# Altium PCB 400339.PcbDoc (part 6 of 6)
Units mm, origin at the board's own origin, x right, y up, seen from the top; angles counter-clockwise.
Board outline 146 x 63.5 mm, 4 copper layers (Top Layer, Mid-Layer 1, Mid-Layer 2, Bottom Layer), stack 1.505 mm thick; 400 components, 261 nets, 1523 pads, 1938 vias.
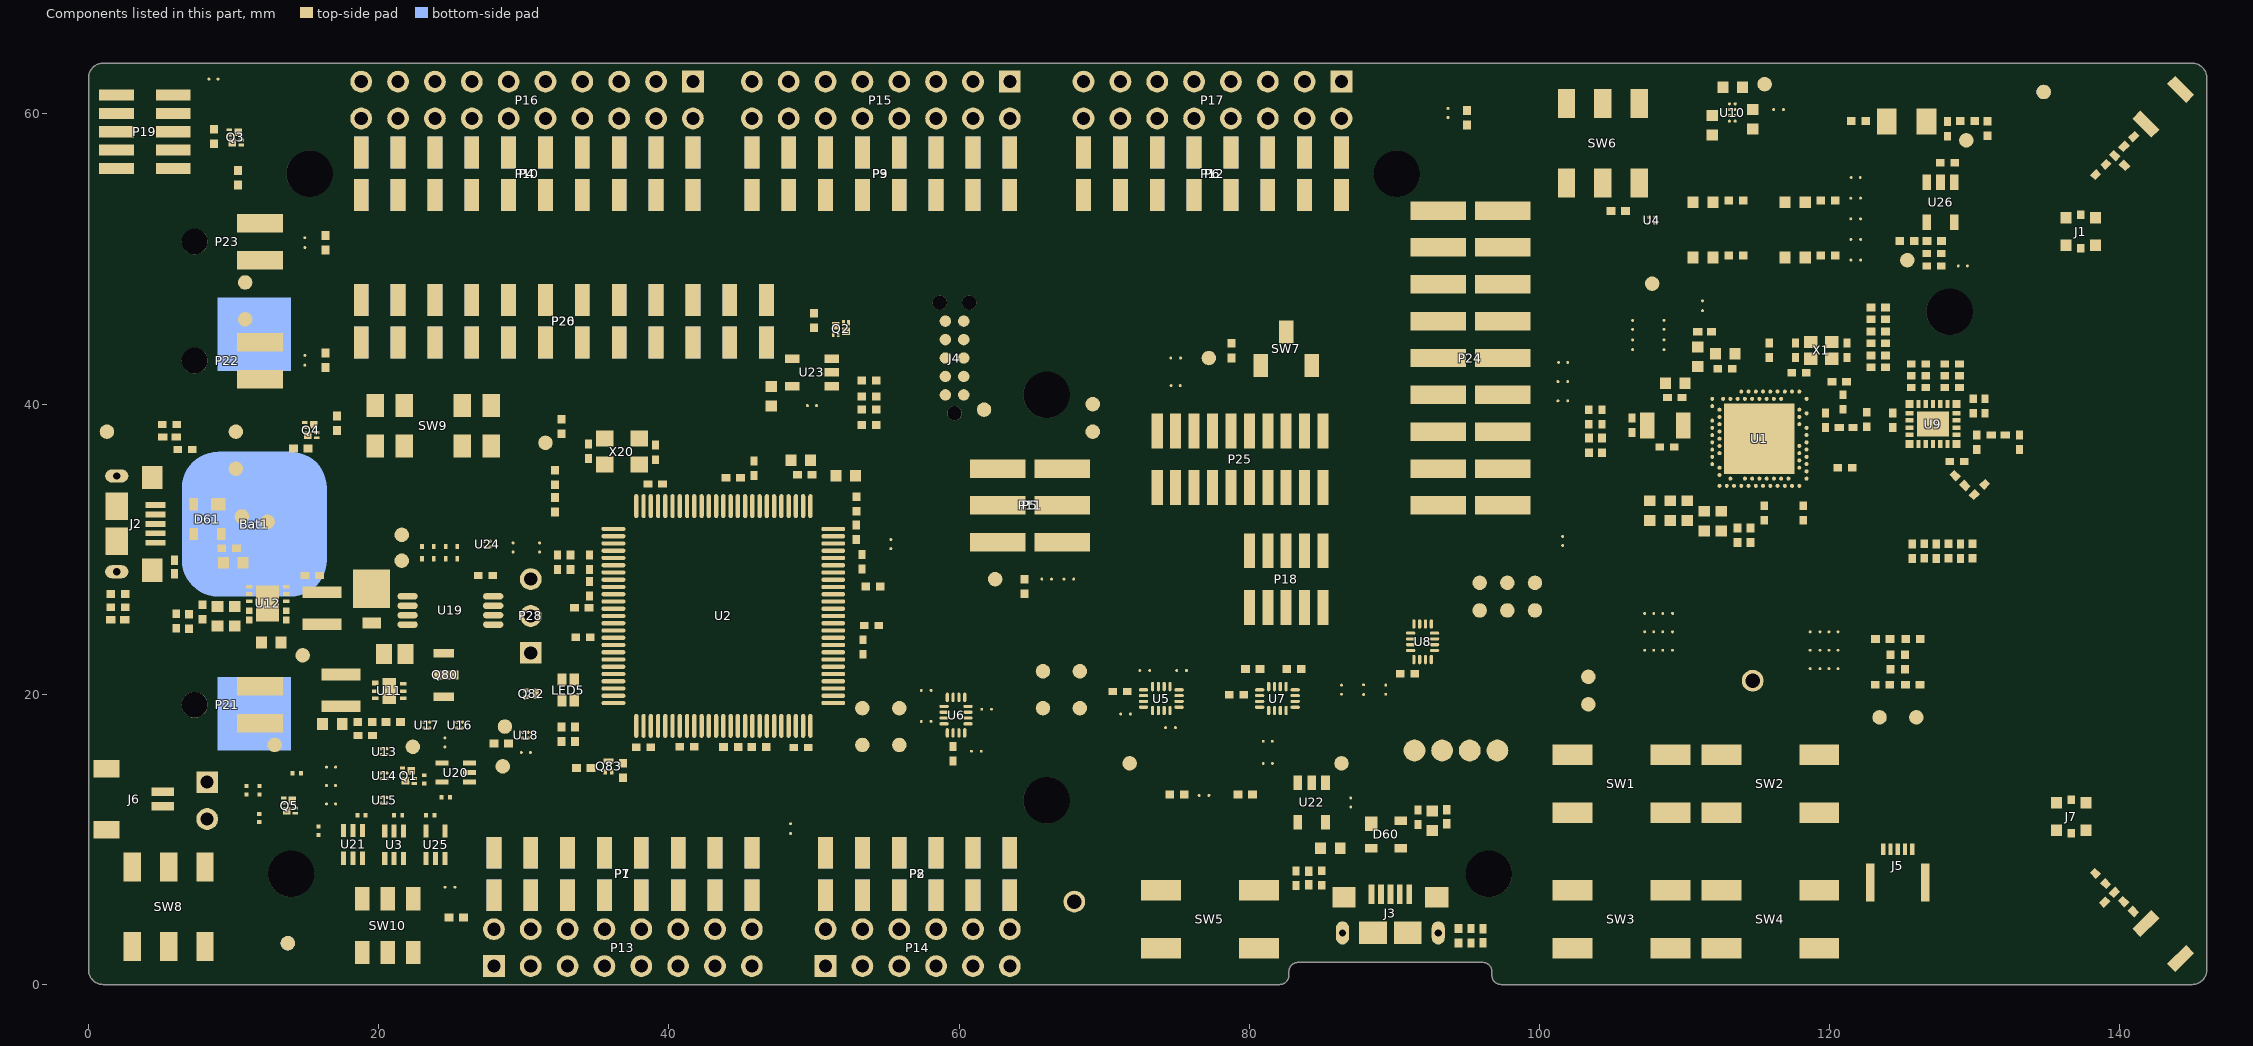
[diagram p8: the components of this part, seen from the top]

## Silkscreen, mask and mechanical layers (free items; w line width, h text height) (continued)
Bottom Overlay:
  drawing of 1284 lines, arcs and shapes, not listed
  text "J-Link" at 117.897,62.424 h1.45 r90
  text "www.segger.com" at 119.047,62.343 h1.68 r90
  text "Pb" at 6.415,60.623 h3.05 r90
  text "TM" at 117.475,58.954 h0.94 r90
  text "S" at 116.037,58.741 h1.35 r90
  text "E" at 116.037,57.851 h1.35 r90
  text "Technology" at 117.897,57.672 h1.45 r90
  text "G" at 116.037,57.067 h1.35 r90
  text "G" at 116.037,56.077 h1.35 r90
  text "E" at 116.037,55.053 h1.35 r90
  text "R" at 116.037,54.217 h1.35 r90
  text "P0.27" at 19.303,53.111 h1.65 r90
  text "P0.26" at 21.843,53.111 h1.65 r90
  text "P0.02" at 24.383,53.111 h1.65 r90
  text "GND" at 26.924,53.111 h1.65 r90
  text "P1.15" at 29.463,53.111 h1.65 r90
  text "P1.14" at 32.003,53.111 h1.65 r90
  text "P1.13" at 34.543,53.111 h1.65 r90
  text "P1.12" at 37.083,53.111 h1.65 r90
  text "P1.11" at 39.623,53.111 h1.65 r90
  text "P1.10" at 42.163,53.111 h1.65 r90
  text "P1.08" at 46.227,53.111 h1.65 r90
  text "P1.07 (D6)" at 48.768,53.111 h1.65 r90
  text "P1.06 (D5)" at 51.308,53.111 h1.65 r90
  text "P1.05 (D4)" at 53.848,53.111 h1.65 r90
  text "P1.04 (D3)" at 56.388,53.111 h1.65 r90
  text "P1.03 (D2)" at 58.928,53.111 h1.65 r90
  text "P1.02 (D1)" at 61.468,53.111 h1.65 r90
  text "P1.01 (ARDUINO D0)" at 64.008,53.111 h1.65 r90
  text "P0.10" at 69.088,53.111 h1.78 r90
  text "P0.09" at 71.628,53.111 h1.78 r90
  text "P0.08" at 74.168,53.111 h1.78 r90
  text "P0.07" at 76.708,53.111 h1.78 r90
  text "P0.06" at 79.248,53.111 h1.78 r90
  text "P0.05" at 81.788,53.111 h1.78 r90
  text "P0.01" at 84.328,53.111 h1.78 r90
  text "P0.00" at 86.843,53.111 h1.78 r90
  text "(SCL)" at 20.421,52.07 h1.65 r90
  text "(SDA)" at 22.961,52.07 h1.65 r90
  text "(AREF)" at 25.501,52.07 h1.65 r90
  text "(D13)" at 30.581,52.07 h1.65 r90
  text "(D12)" at 33.121,52.07 h1.65 r90
  text "(D11)" at 35.661,52.07 h1.65 r90
  text "(D10)" at 38.201,52.07 h1.65 r90
  text "(D9)" at 40.741,52.07 h1.65 r90
  text "(D8)" at 43.281,52.07 h1.65 r90
  text "(D7)" at 47.345,52.07 h1.65 r90
  text "GPIO" at 76.911,48.701 h1.99 r90
  text "P0.00" at 80.747,48.641 h1.91 r90
  text "P0.01" at 86.131,48.641 h1.91 r90
  text "P0.11" at 90.17,48.641 h1.91 r90
  text "P0.12" at 92.862,48.641 h1.91 r90
  text "P0.24" at 95.555,48.641 h1.91 r90
  text "P0.25" at 98.247,48.641 h1.91 r90
  text "P0.13" at 100.94,48.641 h1.91 r90
  text "P0.14" at 103.632,48.641 h1.91 r90
  text "P0.15" at 106.324,48.641 h1.91 r90
  text "P0.16" at 109.017,48.641 h1.91 r90
  text "P0.17" at 111.709,48.641 h1.91 r90
  text "P0.19" at 114.402,48.641 h1.91 r90
  text "P0.20" at 117.094,48.641 h1.91 r90
  text "P0.21" at 119.786,48.641 h1.91 r90
  text "P0.22" at 122.479,48.641 h1.91 r90
  text "P0.23" at 125.171,48.641 h1.91 r90
  text "ANT_SEL" at 125.171,43.514 h1.91 r90
  text "Function" at 76.911,43.231 h1.99 r90
  text "Button 4" at 98.247,42.965 h1.91 r90
  text "Button 2" at 92.862,42.942 h1.91 r90
  text "Button 3" at 95.555,42.949 h1.91 r90
  text "Button 1" at 90.17,42.846 h1.91 r90
  text "LED 4" at 109.017,41.922 h1.91 r90
  text "LED 2" at 103.632,41.899 h1.91 r90
  text "LED 3" at 106.324,41.905 h1.91 r90
  text "GPIO" at 27.33,41.805 h1.99 r90
  text "P0.05" at 29.82,41.783 h1.91 r90
  text "P0.06" at 32.512,41.783 h1.91 r90
  text "P0.07" at 35.204,41.783 h1.91 r90
  text "P0.08" at 37.897,41.783 h1.91 r90
  text "P0.18" at 40.589,41.783 h1.91 r90
  text "P1.00" at 43.282,41.783 h1.91 r90
  text "P0.09" at 52.222,41.783 h1.91 r90
  text "P0.10" at 56.794,41.783 h1.91 r90
  text "LED 1" at 100.94,41.803 h1.91 r90
  text "CTX" at 111.709,41.476 h1.91 r90
  text "CHL" at 114.402,41.476 h1.91 r90
  text "CRX" at 117.094,41.476 h1.91 r90
  text "CPS" at 119.786,41.476 h1.91 r90
  text "CSD" at 122.479,41.476 h1.91 r90
  text "XL2" at 86.131,41.111 h1.91 r90
  text "XL1" at 80.747,41.015 h1.91 r90
  text "SWDCLK" at 48.666,39.218 h1.91 r90
  text "SWDIO" at 45.974,38.329 h1.91 r90
  text "Function" at 27.33,36.335 h1.99 r90
  text "RESET" at 40.564,35.457 h1.91 r90
  text "SB13/23" at 111.709,35.23 h1.91 r90
  text "SB11/21" at 114.402,35.23 h1.91 r90
  text "SB12/22" at 117.094,35.23 h1.91 r90
  text "SB14/24" at 119.786,35.23 h1.91 r90
  text "SB15/25" at 122.479,35.23 h1.91 r90
  text "SB10/20" at 125.171,35.23 h1.91 r90
  text "NFC2" at 56.82,34.816 h1.91 r90
  text "NFC1" at 52.248,34.72 h1.91 r90
  text "SB2" at 79.4,34.671 h1.91 r90
  text "SB4" at 82.093,34.671 h1.91 r90
  text "SB1" at 84.785,34.671 h1.91 r90
  text "SB3" at 87.478,34.671 h1.91 r90
  text "SB5" at 100.94,34.671 h1.91 r90
  text "SB6" at 103.632,34.671 h1.91 r90
  text "SB7" at 106.324,34.671 h1.91 r90
  text "SB8" at 109.017,34.671 h1.91 r90
  text "SWO" at 43.282,34.667 h1.91 r90
  text "RXD" at 37.897,34.39 h1.91 r90
  text "TXD" at 32.512,34.338 h1.91 r90
  text "CTS" at 35.204,34.318 h1.91 r90
  text "RTS" at 29.82,34.296 h1.91 r90
  text "Short" at 76.911,34.155 h1.99 r90
  text "HW" at 27.73,28.448 h1.99 r90
  text "IF / MCU" at 43.409,28.067 h1.78 r90
  text "GPIO" at 85.083,27.927 h1.78 r90
  text "GPIO" at 120.015,27.927 h1.78 r90
  text "GPIO" at 34.773,27.813 h1.78 r90
  text "GPIO" at 57.93,26.381 h1.78 r90
  text "HW" at 76.911,25.519 h1.99 r90
  text "N.C" at 54.864,25.273 h1.27 r90
  text "SB2x" at 115.443,25.057 h1.27 r90
  text "SB1x" at 117.729,25.057 h1.27 r90
  text "PIN" at 50.883,24.171 h1.78 r90
  text "FEM" at 120.015,23.253 h1.78 r90
  text "VDD" at 101.803,23.126 h1.78 r90
  text "PIN" at 80.574,22.364 h1.78 r90
  text "PIN" at 115.57,22.364 h1.78 r90
  text "0R" at 57.658,22.225 h1.27 r90
  text "IF OFF" at 38.735,21.209 h1.78 r90
  text "NFC" at 53.957,21.224 h1.78 r90
  text "Button 2" at 109.017,18.158 h1.91 r90
  text "Button 1" at 106.324,18.061 h1.91 r90
  text "Funct." at 103.835,17.355 h1.99 r90
  text "Function" at 116.916,17.284 h1.78 r90
  text "Default" at 124.714,17.183 h1.78 r90
  text "CTS" at 111.709,16.429 h1.91 r90
  text "P0.03 (A0)" at 51.181,16.012 h1.65 r90
  text "P0.04 (A1)" at 53.721,16.002 h1.65 r90
  text "P0.28 (A2)" at 56.261,16.002 h1.65 r90
  text "P0.29 (A3)" at 58.801,16.002 h1.65 r90
  text "P0.31 (A5)" at 63.881,16.019 h1.65 r90
  text "P0.30 (A4)" at 61.335,15.985 h1.65 r90
  text "RESET" at 33.522,14.272 h1.65 r90
  text "GND" at 43.605,13.103 h1.65 r90
  text "GND" at 41.142,12.95 h1.65 r90
  text "N.C." at 46.272,12.95 h1.78 r90
  text "VDD" at 28.448,12.87 h1.65 r90
  text "VDD" at 30.988,12.87 h1.65 r90
  text "VDD" at 36.068,12.87 h1.65 r90
  text "5V" at 38.633,11.828 h1.65 r90
  text "HW" at 114.249,11.676 h1.99 r90
  text "P0.11" at 106.324,10.579 h1.91 r90
  text "P0.12" at 109.017,10.579 h1.91 r90
  text "P0.07" at 111.709,10.579 h1.91 r90
  text "Def." at 103.835,9.957 h1.99 r90
  text "Alternative" at 124.46,9.055 h1.78 r90
  text "TRACE / SW" at 121.234,8.648 h1.78 r90
  text "P1.07" at 106.324,5.626 h1.91 r90
  text "P1.08" at 109.017,5.626 h1.91 r90
  text "P0.04" at 111.709,5.626 h1.91 r90
  text "Alt." at 103.835,4.691 h1.99 r90
Board Outline:
  the board outline again, w0.254
PCB Info:
  lines w0.165: 8.551,31.901 9.728,31.901 cw(c9.728,31.592) 9.947,31.811 10.031,31.727 ccw(c10.566,32.263) 10.566,31.505 ccw(c10.566,32.259) 11.1,31.726 11.184,31.81 cw(c11.405,31.589) 11.405,31.901 13.147,31.901 ccw(c13.147,32.944) 13.884,32.207 15.112,33.435 ; 8.552,32.259 11.506,32.259 ccw(c11.506,32.571) 11.727,32.35 11.811,32.434 cw(c12.344,31.901) 12.344,32.655 cw(c12.344,31.897) 12.88,32.433 12.964,32.349 ccw(c13.183,32.568) 13.183,32.259 ; 13.153,32.259 ccw(c13.153,32.935) 13.631,32.457 14.84,33.666 ; 14.837,33.669 cw(c16.073,32.433) 16.073,34.181 ; 15.102,33.425 cw(c16.063,32.464) 16.063,33.823 34.407,33.823 ; 16.063,34.181 34.407,34.181 ; 89.242,10.697 89.242,12.23 cw(c91.338,12.23) 91.338,14.326 ccw(c91.338,16.411) 92.813,14.936 94.183,16.307 ; 89.6,10.697 89.6,12.232 cw(c91.338,12.232) 91.338,13.97 ccw(c91.338,16.418) 93.069,14.687 93.522,15.139 ccw(c93.294,16.129) 94.284,15.901 ; 94.204,16.333 cw(c95.199,16.129) 94.995,17.124 ; 94.284,15.902 106.34,27.958 cw(c108.136,26.162) 108.136,28.702 113.295,28.702 ; 94.998,17.121 106.088,28.211 cw(c108.136,26.162) 108.136,29.06 113.295,29.06 ccw(c113.295,29.693) 113.928,29.693 113.928,30.023 ; 112.977,34.061 ccw(c113.89,34.061) 113.244,33.415 113.741,32.918 cw(c113.29,32.467) 113.928,32.467 113.928,32.004 ; 112.982,34.061 112.982,34.299 ; 113.295,28.702 ccw(c113.295,29.693) 114.286,29.693 114.286,30.023 ; 113.335,34.289 113.335,34.061 ccw(c113.89,34.061) 113.498,33.669 113.994,33.172 cw(c113.29,32.467) 114.286,32.467 114.286,32.004
  lines w0.203: 141.798,4.202 cw(c141.798,4.264) 141.754,4.22 ; 141.754,4.22 cw(c141.798,4.264) 141.754,4.22 141.754,4.22
  lines w0.3: 119.718,38.388 120.612,38.388 ; 121.613,38.379 125.503,38.379 ; 128.128,36.207 128.128,37.255 ; 128.275,36.043 128.275,35.933 ccw(c129.449,35.933) 128.619,35.103 ; 129.326,34.396 134.093,29.629 cw(c127.91,23.446) 136.654,23.446 136.654,12.731 ; 132.087,37.868 133.092,37.868 133.096,37.872 ccw(c133.096,42.089) 137.313,42.089 137.313,50.732 ; 136.654,10.411 136.654,10.373 ccw(c139.194,10.373) 137.398,8.577 138.316,7.658 ; 137.313,53.052 137.313,54.376 cw(c138.305,54.376) 137.603,55.078 138.342,55.816 ; 140.268,5.706 139.023,6.951 ; 140.294,57.768 139.049,56.523 ; 140.94,5.035 141.754,4.22 ; 140.965,58.44 cw(c141.027,58.44) 140.983,58.483 141.798,59.298 ; 139.023,6.951 139.023,6.951 ; 139.049,56.523 139.049,56.523 ; 128.753,37.88 131.025,37.88 128.753,37.88
  text "50ohm impedance" at 120.487,39.561 h1.02
  text "90ohm differensial impedance" at 7.417,35.382 h1.02
  text "90ohm differensial impedance" at 90.119,14.402 h1.02 r45
Top Assembly:
  drawing of 47 lines, arcs and shapes, not listed
Bottom Assembly:
  drawing of 47 lines, arcs and shapes, not listed
Panel Info:
  lines w0.165: 8.551,31.901 9.728,31.901 cw(c9.728,31.592) 9.947,31.811 10.031,31.727 ccw(c10.566,32.263) 10.566,31.505 ccw(c10.566,32.259) 11.1,31.726 11.184,31.81 cw(c11.405,31.589) 11.405,31.901 13.147,31.901 ccw(c13.147,32.944) 13.884,32.207 15.112,33.435 ; 8.552,32.259 11.506,32.259 ccw(c11.506,32.571) 11.727,32.35 11.811,32.434 cw(c12.344,31.901) 12.344,32.655 cw(c12.344,31.897) 12.88,32.433 12.964,32.349 ccw(c13.183,32.568) 13.183,32.259 ; 13.153,32.259 ccw(c13.153,32.935) 13.631,32.457 14.84,33.666 ; 14.837,33.669 cw(c16.073,32.433) 16.073,34.181 ; 15.102,33.425 cw(c16.063,32.464) 16.063,33.823 34.407,33.823 ; 16.063,34.181 34.407,34.181 ; 89.242,10.697 89.242,12.23 cw(c91.338,12.23) 91.338,14.326 ccw(c91.338,16.411) 92.813,14.936 94.183,16.307 ; 89.6,10.697 89.6,12.232 cw(c91.338,12.232) 91.338,13.97 ccw(c91.338,16.418) 93.069,14.687 93.522,15.139 ccw(c93.294,16.129) 94.284,15.901 ; 94.204,16.333 cw(c95.199,16.129) 94.995,17.124 ; 94.284,15.902 106.34,27.958 cw(c108.136,26.162) 108.136,28.702 113.295,28.702 ; 94.998,17.121 106.088,28.211 cw(c108.136,26.162) 108.136,29.06 113.295,29.06 ccw(c113.295,29.693) 113.928,29.693 113.928,30.023 ; 112.977,34.061 ccw(c113.89,34.061) 113.244,33.415 113.741,32.918 cw(c113.29,32.467) 113.928,32.467 113.928,32.004 ; 112.982,34.061 112.982,34.299 ; 113.295,28.702 ccw(c113.295,29.693) 114.286,29.693 114.286,30.023 ; 113.335,34.289 113.335,34.061 ccw(c113.89,34.061) 113.498,33.669 113.994,33.172 cw(c113.29,32.467) 114.286,32.467 114.286,32.004
  lines w0.762: 121.681,38.379 126.25,38.379
  text "50ohm impedance" at 115.824,39.37 h1.02
  text "90ohm differensial impedance" at 7.417,35.382 h1.02
  text "90ohm differensial impedance" at 90.119,14.402 h1.02 r45

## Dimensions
144.984,62.484 to 146.187,65.308 on Dimension
0,1.016 to 90.17,55.88 on Dimension
0,1.016 to 145.974,10.16 on Dimension
0,1.016 to 13.97,7.62 on Dimension
0,1.016 to 15.24,55.88 on Dimension
0,1.016 to 66.04,12.7 on Dimension
0,1.016 to 96.52,7.62 on Dimension
144.984,0 to 144.984,63.5 on Dimension
144.984,0 to 96.52,7.62 on Dimension
144.984,0 to 66.04,12.7 on Dimension
144.984,0 to 66.04,40.64 on Dimension
144.984,0 to 15.24,55.88 on Dimension
144.984,0 to 128.27,46.355 on Dimension
0,1.016 to 128.27,46.355 on Dimension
